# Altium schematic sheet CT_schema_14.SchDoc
size 389 x 385 mm
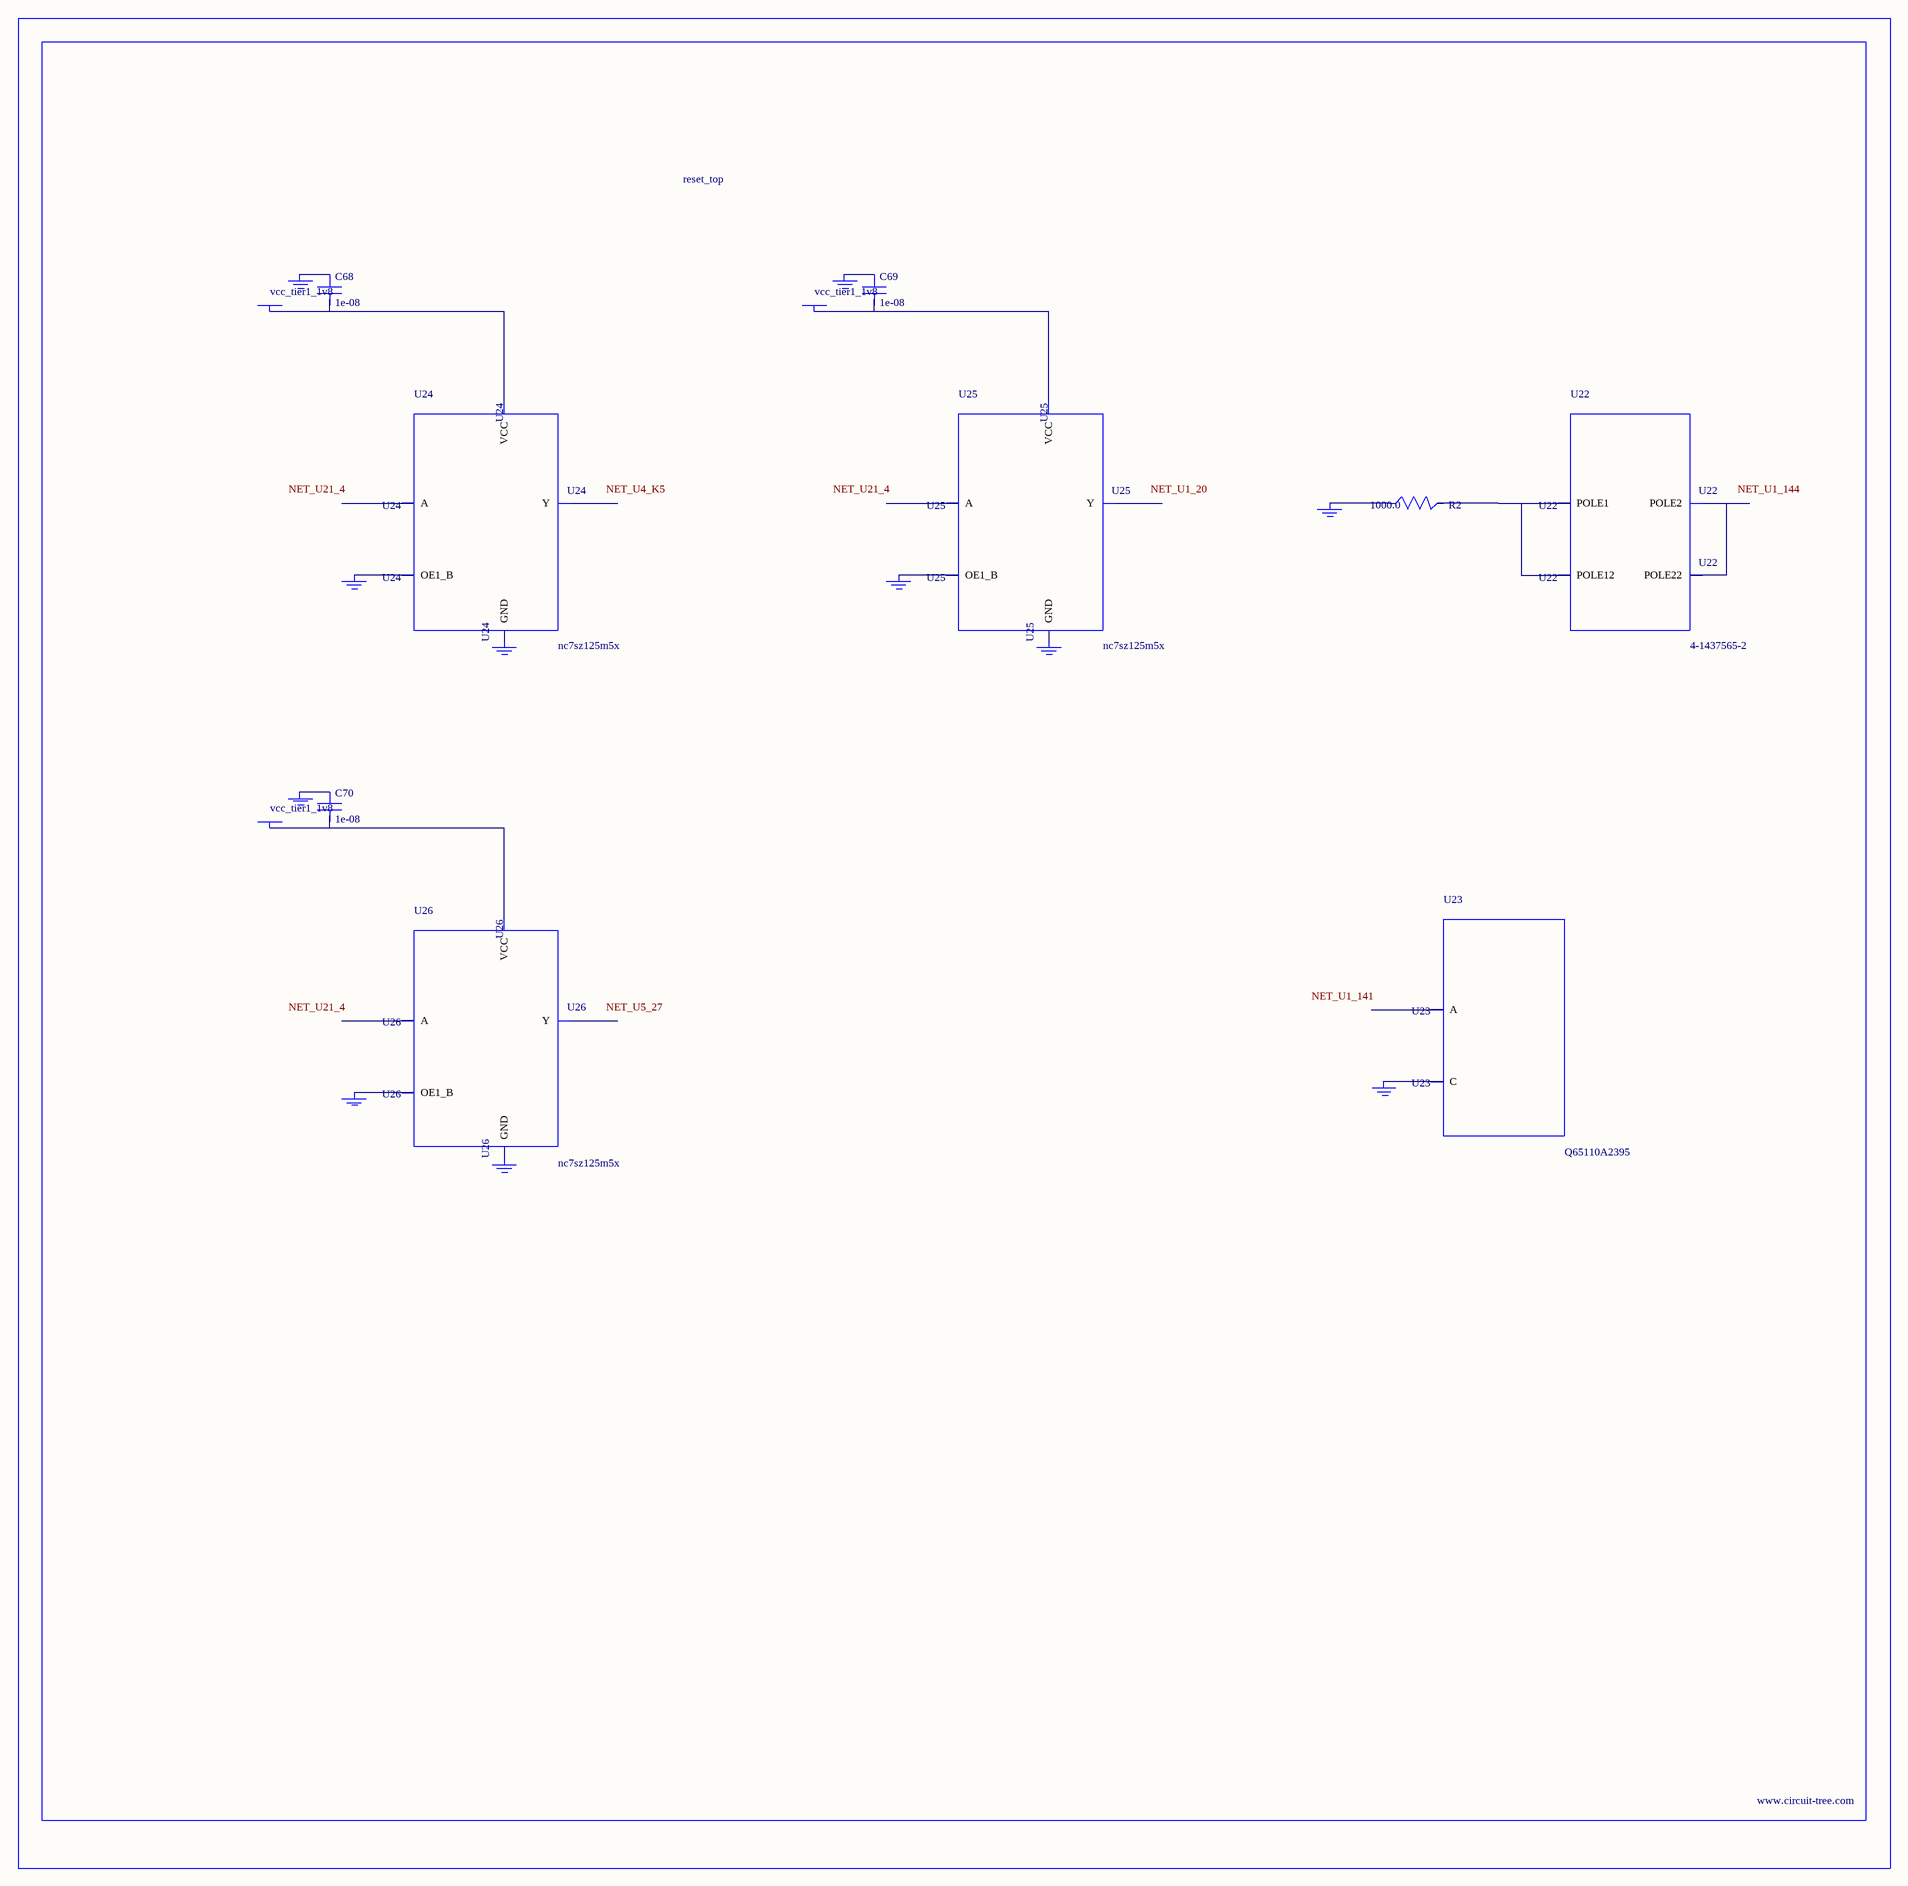
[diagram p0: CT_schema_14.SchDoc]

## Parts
BORDER13  (no value)
C68  1e-08  [C0402]
C69  1e-08  [C0402]
C70  1e-08  [C0402]
GND_INSTANCE_13_0  (no value)
GND_INSTANCE_13_1  (no value)
GND_INSTANCE_13_2  (no value)
GND_INSTANCE_13_3  (no value)
GND_INSTANCE_13_4  (no value)
GND_INSTANCE_13_5  (no value)
GND_INSTANCE_13_6  (no value)
GND_INSTANCE_13_7  (no value)
GND_INSTANCE_13_8  (no value)
GND_INSTANCE_13_9  (no value)
GND_INSTANCE_13_10  (no value)
POWER_INSTANCE_13_0  vcc_tier1_1v8
POWER_INSTANCE_13_1  vcc_tier1_1v8
POWER_INSTANCE_13_2  vcc_tier1_1v8
R2  1000.0  [R0603]
U22  4-1437565-2  [SW_4-1437565-2]
U23  Q65110A2395  [LGM67K-G1J2-24-Z]
U24  nc7sz125m5x  [NC7SZ125M5X]
U25  nc7sz125m5x  [NC7SZ125M5X]
U26  nc7sz125m5x  [NC7SZ125M5X]

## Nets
NetC68_1: C68.1 GND_INSTANCE_13_2.0(GND)
NetC68_2: C68.2 POWER_INSTANCE_13_0.0(PWR) U24.5(VCC)
NetC69_1: C69.1 GND_INSTANCE_13_5.0(GND)
NetC69_2: C69.2 POWER_INSTANCE_13_1.0(PWR) U25.5(VCC)
NetC70_1: C70.1 GND_INSTANCE_13_8.0(GND)
NetC70_2: C70.2 POWER_INSTANCE_13_2.0(PWR) U26.5(VCC)
NetGND_INSTANCE_13_0_0: GND_INSTANCE_13_0.0(GND) R2.1
NetGND_INSTANCE_13_1_0: GND_INSTANCE_13_1.0(GND) U23.C
NetGND_INSTANCE_13_3_0: GND_INSTANCE_13_3.0(GND) U24.1(OE1_B)
NetGND_INSTANCE_13_4_0: GND_INSTANCE_13_4.0(GND) U24.3(GND)
NetGND_INSTANCE_13_6_0: GND_INSTANCE_13_6.0(GND) U25.1(OE1_B)
NetGND_INSTANCE_13_7_0: GND_INSTANCE_13_7.0(GND) U25.3(GND)
NetGND_INSTANCE_13_9_0: GND_INSTANCE_13_9.0(GND) U26.1(OE1_B)
NetGND_INSTANCE_13_10_0: GND_INSTANCE_13_10.0(GND) U26.3(GND)
NetR2_2: R2.2 U22.1(POLE1) U22.2(POLE12)
NetU22_3: U22.3(POLE2) U22.4(POLE22)

Not connected (* = marked no-connect by the designer): U23 A; U24 2(A) 4(Y); U25 2(A) 4(Y); U26 2(A) 4(Y)

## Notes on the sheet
- Labels drawn without touching a wire or pin: NET_U1_20, NET_U1_141, NET_U1_144, NET_U4_K5, NET_U5_27, NET_U21_4

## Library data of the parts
BORDER13 = BORDER_PAGE13
C68-C70 = C0402C103K3RAC
GND_INSTANCE_13_0-GND_INSTANCE_13_10 = GND
POWER_INSTANCE_13_0-POWER_INSTANCE_13_2 = PWR
R2 = RC0603JR-071KL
